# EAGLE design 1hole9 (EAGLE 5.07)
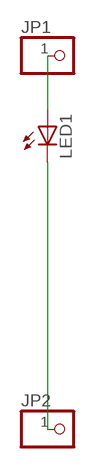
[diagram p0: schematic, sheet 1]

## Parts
JP1  PINHD-1X11MM6  [1X1MM8]
JP2  PINHD-1X11MM6  [1X1MM8]
LED1  LED1W_HOLE  [1W]

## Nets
A: JP1.1 LED1.A
C: JP2.1 LED1.C

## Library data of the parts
JP1 JP2 = pinhead:PINHD-1X1: PIN HEADER
LED1 = led:LED: LED

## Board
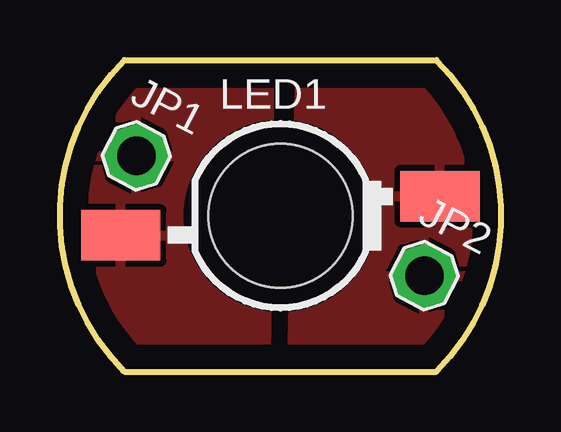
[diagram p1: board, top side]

Size 18.37 x 13 mm. Coordinates in mm from the lower left corner, seen from the top.
Outline: 2.68,0 15.68,0 arc90 15.68,13 2.68,13 arc90 2.68,0
Copper layers (1*16): Top 0.035mm / dielectric 1.5mm / Bottom 0.035mm
Design rules "default": minimum track width 10mil, minimum drill 24mil, track to track 8mil, track to pad 8mil, pad to pad 8mil, via to via 8mil, smd to smd 8mil, copper to edge 40mil, drill to drill 8mil, minimum pad ring 10mil, minimum via ring 8mil, stop-mask expansion 4mil, vias tented up to drill 0mil, thermal gap 10mil

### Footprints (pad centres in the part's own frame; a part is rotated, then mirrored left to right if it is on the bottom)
1X1MM8 = drill 1.6 pad 2.54 octagon: 1 0,0
1W = smd 3.3 x 2.1: A -6.65,-0.82; C 6.65,0.82 | hole 6: 0,0

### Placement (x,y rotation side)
JP1  3.18,9 332.5 top
JP2  15.18,4 332.5 top
LED1  9.18,6.5 0 top

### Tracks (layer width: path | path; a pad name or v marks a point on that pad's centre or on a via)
A
  pour Top: 2.82,12.28 8.73,12.44 8.58,0.5 2.49,0.4 arc-99 2.36,11.39
C
  pour Top: 15.89,12.64 arc-74 15.73,0.41 9.67,0.57 10,12.42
